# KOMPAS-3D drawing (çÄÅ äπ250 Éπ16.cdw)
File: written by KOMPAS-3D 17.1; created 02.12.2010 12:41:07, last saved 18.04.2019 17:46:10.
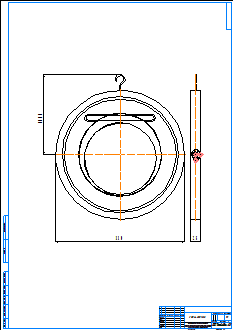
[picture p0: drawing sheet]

Sheet 1: A1, portrait

Title block, sheet 1: name: ЗОП Ду250 Ру16; material: Внимание! Данный продукт является объектом авторского права ООО «Торговый Дом АДЛ». / Запрещается изменение, копирование, распространение / (в том числе путем копирования на другие сайты и ресурсы в Интернете) / или любое иное использование информации и объектов без предварительного / согласия правообладателя (ООО «Торговый Дом АДЛ»).; scale: 1:1; sheets: 1; organisation: ООО "Торговый дом АДЛ"; sheet format: A1; stored path: \\adlc.lan\data\АДЛ_ПКД\3D-модели\ADL production\Клапаны обратные ГРАНЛОК\ЗОП\KOMPAS 2D\ЗОП Ду250 Ру16.cdw

Views: Спереди 1, Проекционный вид 2
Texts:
  bsv
  adl
Dimensions and other numbers on the sheet: 330; 25; 205,8; 1:1; 1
